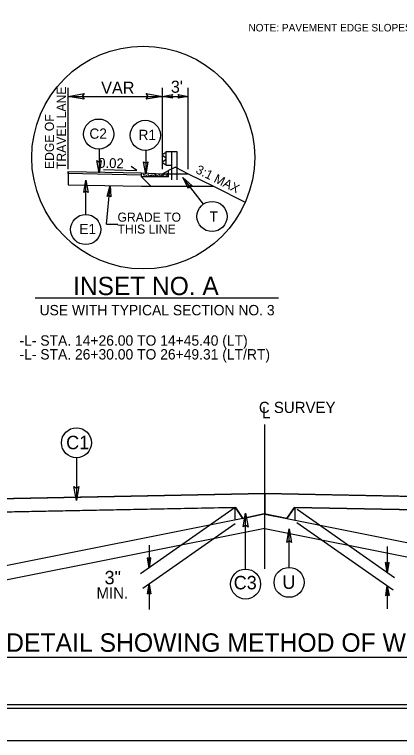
# Model space of a CAD drawing. Extents: x 573687 to 575553, y -54556 to -52223.
# Drawn here: x 574841 to 575109, y -53323 to -52818 of the extents above; entities that cross this region are included whole.
import ezdxf

# ---------------------------------------------------------------- set-up
doc = ezdxf.new("R2010")
doc.units = 0
for name, color, linetype in [('Default', 7, 'Continuous'), ('Old_Level_1', 7, 'Continuous'), ('Old_Level_11', 7, 'Continuous'), ('Prop Dimension', 7, 'Continuous'), ('Prop Dimension Text', 7, 'Continuous'), ('Sheet Cutting Line CELL', 7, 'Continuous'), ('Sheet Plot Border Inside CELL', 7, 'Continuous'), ('Sheet Plot Border Outside CELL', 7, 'Continuous'), ('Sheet Typical CELL', 7, 'Continuous'), ('Typical Arrow Superelevation CELL', 7, 'Continuous'), ('Typical Curb CELL', 7, 'Continuous'), ('Typical Detail Wedge2 CELL', 7, 'Continuous'), ('Typical Guardrail CELL', 7, 'Continuous'), ('Typical ID Circle CELL', 7, 'Continuous'), ('Typical Terminator CELL', 7, 'Continuous'), ('Typical Text Centerline CELL', 7, 'Continuous'), ('Typical Text Label CELL', 7, 'Continuous')]:
    doc.layers.add(name, color=color, linetype=linetype)

msp = doc.modelspace()

# ---------------------------------------------------------------- linework, layer by layer
at = {"layer": 'Old_Level_1'}
for p, q in [((574878.6, -52927.44), (574878.6, -52936.69)), ((574878.6, -52927.44), (574929.53, -52928.46)), ((574878.6, -52928.94), (574878.6, -52927.44)), ((574953.11, -52924.48), (574948.41, -52926.83)), ((574953.11, -52924.48), (574962.11, -52928.98)), ((574929.5, -52929.96), (574878.6, -52928.94)), ((574929.53, -52931.06), (574936.18, -52937.71)), ((574944.11, -52928.98), (574962.11, -52928.98)), ((574962.11, -52928.98), (574979.57, -52937.71)), ((574878.6, -52936.69), (574929.53, -52937.71)), ((574929.53, -52937.71), (574958.05, -52937.71)), ((574958.05, -52937.71), (574979.57, -52937.71)), ((574979.57, -52937.71), (575001.69, -52948.77)), ((574855.71, -53015.13), (575024.67, -53015.13))]:
    msp.add_line(p, q, dxfattribs=at)
msp.add_circle((574930.8, -52917.75), 77.38, dxfattribs=at)
at = {"layer": 'Old_Level_11'}
for q in [(574907.82, -52937.28), (574913.25, -52963.93)]:
    msp.add_line((574905.28, -52963.93), q, dxfattribs=at)
for points in [[(574889.85, -52877.18), (574878.6, -52875.25), (574889.91, -52873.25), (574888.47, -52875.25)], [(574932.86, -52873.31), (574944.11, -52875.25), (574932.8, -52877.25), (574934.23, -52875.25)], [(574905.77, -52944.72), (574907.82, -52937.28), (574908.43, -52944.97), (574907.19, -52943.91)]]:
    msp.add_lwpolyline(points, close=True, dxfattribs=at)
at = {"layer": 'Prop Dimension'}
for p, q in [((574878.6, -52925.89), (574878.6, -52869.25)), ((574944.11, -52925.89), (574944.11, -52869.25)), ((574962.11, -52925.89), (574962.11, -52869.25)), ((574878.6, -52875.25), (574944.11, -52875.25)), ((574944.11, -52875.25), (574962.11, -52875.25)), ((574900.26, -52911.9), (574900.27, -52928.46)), ((574932.63, -52912.77), (574932.63, -52929.33)), ((574972.63, -52950.08), (574958.2, -52931.55)), ((574891, -52957.3), (574891, -52933.45)), ((575015.22, -53203.45), (575015.22, -53103.25))]:
    msp.add_line(p, q, dxfattribs=at)
for points in [[(575015.22, -53165.42), (575015.22, -53151.04), (575015.22, -53151.04), (574782.37, -53155.69), (574782.34, -53155.91), (574782.48, -53157.18), (574781.08, -53164.8), (574781.05, -53165.05), (574945.34, -53161.76), (574980.06, -53161.07), (574994.79, -53160.77), (575000.02, -53168.44), (575014.87, -53165.35), (575015.22, -53165.42), (575015.22, -53165.42)], [(575015.22, -53151.04), (575015.22, -53165.42), (575015.22, -53165.42), (575030.42, -53168.44), (575035.69, -53160.96), (575035.82, -53160.77), (575050.38, -53161.07), (575085.1, -53161.76), (575085.1, -53161.76), (575085.1, -53161.76), (575249.4, -53165.04), (575247.96, -53157.18), (575248.1, -53155.87), (575248.08, -53155.69), (575015.24, -53151.04), (575015.22, -53151.04)]]:
    msp.add_lwpolyline(points, dxfattribs=at)
for centre in [(574899.88, -52901.45), (574932.24, -52902.32), (574978.58, -52958.68), (574890.88, -52967.76)]:
    msp.add_circle(centre, 10.46, dxfattribs=at)
at = {"layer": 'Prop Dimension Text'}
msp.add_line((574833.54, -53264.81), (575194.71, -53264.81), dxfattribs=at)
at = {"layer": 'Sheet Cutting Line CELL'}
msp.add_line((573687.43, -53322.67), (575371.43, -53322.67), dxfattribs=at)
at = {"layer": 'Sheet Plot Border Inside CELL'}
msp.add_lwpolyline([(575366.93, -52245.12), (573700.43, -52245.12), (573700.43, -53300.22), (575366.93, -53300.22)], close=True, dxfattribs=at)
at = {"layer": 'Sheet Plot Border Outside CELL'}
msp.add_lwpolyline([(575371.43, -52222.67), (573687.43, -52222.67), (573687.43, -53322.67), (575371.43, -53322.67)], close=True, dxfattribs=at)
at = {"layer": 'Sheet Typical CELL'}
msp.add_lwpolyline([(575354.43, -52247.67), (573854.43, -52247.67), (573854.43, -53297.67), (575354.43, -53297.67)], close=True, dxfattribs=at)
at = {"layer": 'Typical Arrow Superelevation CELL'}
for p, q in [((574903.22, -52925.99), (574926.44, -52926.66)), ((574926.44, -52926.66), (574922.55, -52924.03))]:
    msp.add_line(p, q, dxfattribs=at)
at = {"layer": 'Typical Curb CELL'}
for p, q in [((574944.11, -52928.98), (574948.41, -52926.83)), ((574948.41, -52931.06), (574948.41, -52926.83)), ((574929.53, -52928.46), (574929.53, -52928.46)), ((574929.53, -52931.06), (574929.53, -52928.53)), ((574948.41, -52931.06), (574929.53, -52931.06)), ((574929.6, -52928.46), (574944.11, -52928.98)), ((574931.01, -52930.11), (574931.55, -52929.36)), ((574931.77, -52930.07), (574931.01, -52930.11)), ((574931.55, -52929.36), (574931.77, -52930.07)), ((574935.8, -52930.43), (574936.19, -52929.72)), ((574936.83, -52930.18), (574935.8, -52930.43)), ((574936.19, -52929.72), (574936.83, -52930.18)), ((574938.82, -52930.11), (574939.36, -52929.36)), ((574939.57, -52930.07), (574938.82, -52930.11)), ((574939.36, -52929.36), (574939.57, -52930.07)), ((574943.6, -52930.43), (574943.99, -52929.72)), ((574944.64, -52930.18), (574943.6, -52930.43)), ((574943.99, -52929.72), (574944.64, -52930.18)), ((574947.21, -52928.91), (574947.32, -52929.48)), ((574948.18, -52929.19), (574947.21, -52928.91)), ((574947.32, -52929.48), (574948.18, -52929.19))]:
    msp.add_line(p, q, dxfattribs=at)
for centre in [(574930.09, -52929.57), (574930.33, -52928.79), (574932.62, -52929.25), (574932.99, -52930.37), (574933.34, -52930.58), (574933.55, -52929.79), (574934.02, -52929.8), (574934.33, -52929.61), (574934.63, -52930.33), (574935.84, -52930.09), (574937.13, -52930.19), (574937.23, -52929.87), (574937.3, -52929.5), (574937.65, -52930.4), (574938.25, -52930.11), (574938.84, -52930.05), (574939.59, -52930.37), (574940.8, -52930.37), (574941.15, -52930.58), (574941.36, -52929.79), (574942.14, -52929.61), (574942.43, -52930.33), (574943.65, -52930.09), (574943.83, -52930.72), (574944.93, -52930.19), (574945.04, -52929.87), (574946.64, -52930.05), (574947.39, -52930.37), (574948, -52928.66)]:
    msp.add_circle(centre, 0.0501, dxfattribs=at)
msp.add_arc((574929.59, -52928.53), 0.0651, 87.952, 180, dxfattribs=at)
at = {"layer": 'Typical Detail Wedge2 CELL'}
for p, q in [((575015.22, -53203.45), (575015.22, -53122.42)), ((575015.22, -53151.04), (574782.37, -53155.69)), ((574782.37, -53155.69), (575015.22, -53151.04)), ((575015.22, -53151.04), (575248.08, -53155.69)), ((575015.24, -53151.04), (575248.08, -53155.69)), ((574994.79, -53160.77), (574781.05, -53165.05)), ((574994.79, -53160.77), (574781.05, -53165.05)), ((574994.53, -53160.95), (574928.92, -53206.9)), ((574994.49, -53160.86), (574994.49, -53168.97)), ((575000.02, -53168.44), (574994.79, -53160.77)), ((574994.79, -53161.02), (575000.02, -53168.44)), ((575035.82, -53160.77), (575030.42, -53168.44)), ((575035.82, -53160.77), (575030.42, -53168.44)), ((575035.48, -53160.95), (575035.81, -53160.96)), ((575035.82, -53160.77), (575249.41, -53165.05)), ((575249.41, -53165.05), (575035.82, -53160.77)), ((575035.96, -53160.86), (575035.96, -53169.8)), ((575037.6, -53162.02), (575105.19, -53209.35)), ((575000.02, -53168.44), (574784.12, -53211.67)), ((575014.87, -53165.35), (575000.02, -53168.44)), ((575030.42, -53168.44), (575014.87, -53165.35)), ((575030.42, -53168.44), (575246.33, -53211.66)), ((574994.68, -53172.18), (574930.48, -53217.12)), ((575037.51, -53171.22), (575104.44, -53218.08)), ((575015.13, -53175.32), (574784.04, -53221.54)), ((575015.31, -53175.32), (575246.94, -53221.65)), ((574934.9, -53187.1), (574934.9, -53202.7)), ((575100.25, -53187.99), (575100.25, -53205.89)), ((574934.9, -53202.7), (574933.69, -53195.86)), ((574934.9, -53196.75), (574933.69, -53195.86)), ((574934.9, -53202.7), (574933.86, -53195.99)), ((574934.03, -53196.12), (574934.9, -53202.7)), ((574934.9, -53202.7), (574934.2, -53196.24)), ((574934.38, -53196.37), (574934.9, -53202.7)), ((574934.9, -53202.7), (574934.55, -53196.5)), ((574934.73, -53196.62), (574934.9, -53202.7)), ((574934.9, -53202.7), (574936.11, -53195.86)), ((574936.11, -53195.86), (574934.9, -53196.75)), ((574935.94, -53195.99), (574934.9, -53202.7)), ((574934.9, -53202.7), (574935.75, -53196.12)), ((574935.58, -53196.24), (574934.9, -53202.7)), ((574934.9, -53202.7), (574935.41, -53196.37)), ((574935.24, -53196.5), (574934.9, -53202.7)), ((574934.9, -53202.7), (574935.07, -53196.62)), ((574934.9, -53196.75), (574934.9, -53202.7)), ((575100.25, -53205.89), (575099.04, -53199.04)), ((575100.25, -53199.93), (575099.04, -53199.04)), ((575100.25, -53205.89), (575099.22, -53199.17)), ((575099.39, -53199.29), (575100.25, -53205.89)), ((575100.25, -53205.89), (575099.56, -53199.42)), ((575099.73, -53199.55), (575100.25, -53205.89)), ((575100.25, -53205.89), (575099.9, -53199.67)), ((575100.07, -53199.8), (575100.25, -53205.89)), ((575100.25, -53205.89), (575101.46, -53199.04)), ((575101.46, -53199.04), (575100.25, -53199.93)), ((575101.28, -53199.17), (575100.25, -53205.89)), ((575100.25, -53205.89), (575101.11, -53199.29)), ((575100.94, -53199.42), (575100.25, -53205.89)), ((575100.25, -53205.89), (575100.77, -53199.55)), ((575100.59, -53199.67), (575100.25, -53205.89)), ((575100.25, -53205.89), (575100.42, -53199.8)), ((575100.25, -53199.93), (575100.25, -53205.89)), ((574934.9, -53214.03), (574933.69, -53220.88)), ((574933.86, -53220.75), (574934.9, -53214.03)), ((574934.9, -53214.03), (574934.03, -53220.63)), ((574934.2, -53220.49), (574934.9, -53214.03)), ((574934.9, -53214.03), (574934.38, -53220.37)), ((574934.55, -53220.25), (574934.9, -53214.03)), ((574934.9, -53214.03), (574934.73, -53220.12)), ((574934.9, -53214.03), (574934.9, -53231.61)), ((574934.9, -53214.03), (574936.11, -53220.88)), ((574934.9, -53219.99), (574934.9, -53214.03)), ((574935.07, -53220.12), (574934.9, -53214.03)), ((574934.9, -53214.03), (574935.24, -53220.25)), ((574935.41, -53220.37), (574934.9, -53214.03)), ((574934.9, -53214.03), (574935.58, -53220.49)), ((574935.75, -53220.63), (574934.9, -53214.03)), ((574934.9, -53214.03), (574935.94, -53220.75)), ((574933.69, -53220.88), (574934.9, -53219.99)), ((574934.9, -53219.99), (574936.11, -53220.88)), ((575100.25, -53215.15), (575099.04, -53222)), ((575099.22, -53221.86), (575100.25, -53215.15)), ((575100.25, -53215.15), (575099.39, -53221.74)), ((575099.56, -53221.6), (575100.25, -53215.15)), ((575100.25, -53215.15), (575099.73, -53221.48)), ((575099.9, -53221.36), (575100.25, -53215.15)), ((575100.25, -53215.15), (575100.07, -53221.23)), ((575100.25, -53215.15), (575100.25, -53231.15)), ((575100.25, -53215.15), (575101.46, -53222)), ((575100.25, -53221.11), (575100.25, -53215.15)), ((575100.42, -53221.23), (575100.25, -53215.15)), ((575100.25, -53215.15), (575100.59, -53221.36)), ((575100.77, -53221.48), (575100.25, -53215.15)), ((575100.25, -53215.15), (575100.94, -53221.6)), ((575101.11, -53221.74), (575100.25, -53215.15)), ((575100.25, -53215.15), (575101.28, -53221.86)), ((575099.04, -53222), (575100.25, -53221.11)), ((575100.25, -53221.11), (575101.46, -53222))]:
    msp.add_line(p, q, dxfattribs=at)
at = {"layer": 'Typical Guardrail CELL'}
for p, q in [((574944.45, -52915.33), (574945.73, -52914.43)), ((574944.45, -52916.36), (574946.14, -52917.53)), ((574945.83, -52914.39), (574946.41, -52914.29)), ((574954.45, -52913.7), (574946.41, -52913.7)), ((574946.41, -52913.7), (574946.41, -52923.08)), ((574950.43, -52913.73), (574950.43, -52933.31)), ((574954.45, -52933.31), (574954.45, -52913.73)), ((574944.45, -52920.43), (574946.14, -52919.25)), ((574944.45, -52921.46), (574945.73, -52922.36)), ((574945.85, -52922.4), (574946.41, -52922.49)), ((574946.41, -52923.08), (574950.43, -52923.08))]:
    msp.add_line(p, q, dxfattribs=at)
for points in [[(574951.24, -52876.5), (574944.11, -52875.25), (574951.24, -52874), (574950.36, -52875.25)], [(574954.98, -52874), (574962.11, -52875.25), (574954.98, -52876.5), (574955.86, -52875.25)]]:
    msp.add_lwpolyline(points, close=True, dxfattribs=at)
for centre, radius, start, end in [((574944.82, -52915.84), 0.628, 125.0033, 234.9967), ((574945.87, -52914.64), 0.252, 100.0493, 125.0389), ((574944.82, -52920.95), 0.628, 125.0033, 234.9967), ((574945.87, -52922.15), 0.252, 234.9611, 266.1456), ((574945.78, -52918.05), 0.628, 0, 54.9829), ((574945.78, -52918.74), 0.628, 305.0171, 0)]:
    msp.add_arc(centre, radius, start, end, dxfattribs=at)
at = {"layer": 'Typical ID Circle CELL'}
for p, q in [((574884.45, -53126.29), (574884.45, -53155.95)), ((575001.89, -53203.63), (575001.89, -53164.74)), ((575032.07, -53202.43), (575032.07, -53175.55))]:
    msp.add_line(p, q, dxfattribs=at)
for centre in [(574884.45, -53115.89), (575001.89, -53214.03), (575032.07, -53212.83)]:
    msp.add_circle(centre, 10.4, dxfattribs=at)
at = {"layer": 'Typical Terminator CELL'}
for points in [[(574901.67, -52919.84), (574900.27, -52928.46), (574898.66, -52919.82), (574900.2, -52920.9)], [(574934.03, -52920.71), (574932.63, -52929.33), (574931.02, -52920.69), (574932.56, -52921.77)], [(574962.32, -52939.25), (574958.2, -52931.55), (574964.72, -52937.44), (574962.84, -52937.51)], [(574889.52, -52942.06), (574891, -52933.45), (574892.53, -52942.1), (574891, -52941)], [(574886.11, -53146.32), (574884.45, -53155.95), (574882.73, -53146.27), (574884.45, -53147.5)], [(575000.23, -53174.37), (575001.89, -53164.74), (575003.6, -53174.42), (575001.89, -53173.19)], [(575030.41, -53185.18), (575032.07, -53175.55), (575033.78, -53185.23), (575032.07, -53184)]]:
    msp.add_lwpolyline(points, close=True, dxfattribs=at)

# ---------------------------------------------------------------- texts
at = {"layer": 'Default'}
for s, height, p in [('NOTE: PAVEMENT EDGE SLOPES ARE 1:1 UNLESS SHOWN OTHERWISE.', 5.224, (575003.82, -52830.16)), ('-L- STA. 14+26.00 TO 14+45.40 (LT)', 7.2, (574844.92, -53048.44)), ('-L- STA. 26+30.00 TO 26+49.31 (LT/RT)', 7.2, (574844.92, -53058.04))]:
    msp.add_text(s, height=height, dxfattribs=at).set_placement(p)
at = {"layer": 'Prop Dimension Text'}
for s, height, p in [('C2', 7.113, (574893.45, -52904.69)), ('R1', 7.113, (574927.56, -52905.56)), ('T', 7.11, (574976.85, -52962.31)), ('E1', 7.113, (574886.46, -52970.93))]:
    msp.add_text(s, height=height, dxfattribs=at).set_placement(p)
for s, p in [('C1', (574877.31, -53120.35)), ('C3', (574993.63, -53217.69)), ('U', (575027.41, -53217.37))]:
    msp.add_text(s, height=9.35, rotation=0.0001, dxfattribs=at).set_placement(p)
at = {"layer": 'Typical Detail Wedge2 CELL'}
for s, height, p in [('3"', 9.309, (574904.01, -53214.16)), ('MIN.', 7.779, (574898.39, -53224.06))]:
    msp.add_text(s, height=height, rotation=0.0001, dxfattribs=at).set_placement(p)
at = {"layer": 'Typical Text Centerline CELL'}
for s, height, p in [('C SURVEY ', 7.779, (575011.11, -53095.2)), ('L', 7.78, (575013.38, -53098.84))]:
    msp.add_text(s, height=height, rotation=0.0001, dxfattribs=at).set_placement(p)
at = {"layer": 'Typical Text Label CELL'}
for s, height, p in [('VAR', 8.415, (574901.61, -52873.47)), ("3'", 8.415, (574949.98, -52872.77)), ('GRADE TO', 6.311, (574912.97, -52962.31)), ('THIS LINE', 6.311, (574912.97, -52970.59))]:
    msp.add_text(s, height=height, dxfattribs=at).set_placement(p)
for s, height, rotation, p in [('TRAVEL LANE', 6.3112, 90, (574877.1, -52925.71)), ('EDGE OF', 6.311, 90, (574868.83, -52925.71)), (' 0.02', 6.835, 358.8083, (574896.92, -52924.8)), ('3:1 MAX', 6.311, 333.4349, (574966.72, -52928.2)), ('INSET NO. A', 12.7159, 360, (574882.13, -53013.31)), ('USE WITH TYPICAL SECTION NO. 3', 7.2, 360, (574858.85, -53027.35)), ('DETAIL SHOWING METHOD OF WEDGING', 12.8401, 0.0001, (574835.6, -53261.09))]:
    msp.add_text(s, height=height, rotation=rotation, dxfattribs=at).set_placement(p)

doc.saveas('drawing.dxf')
